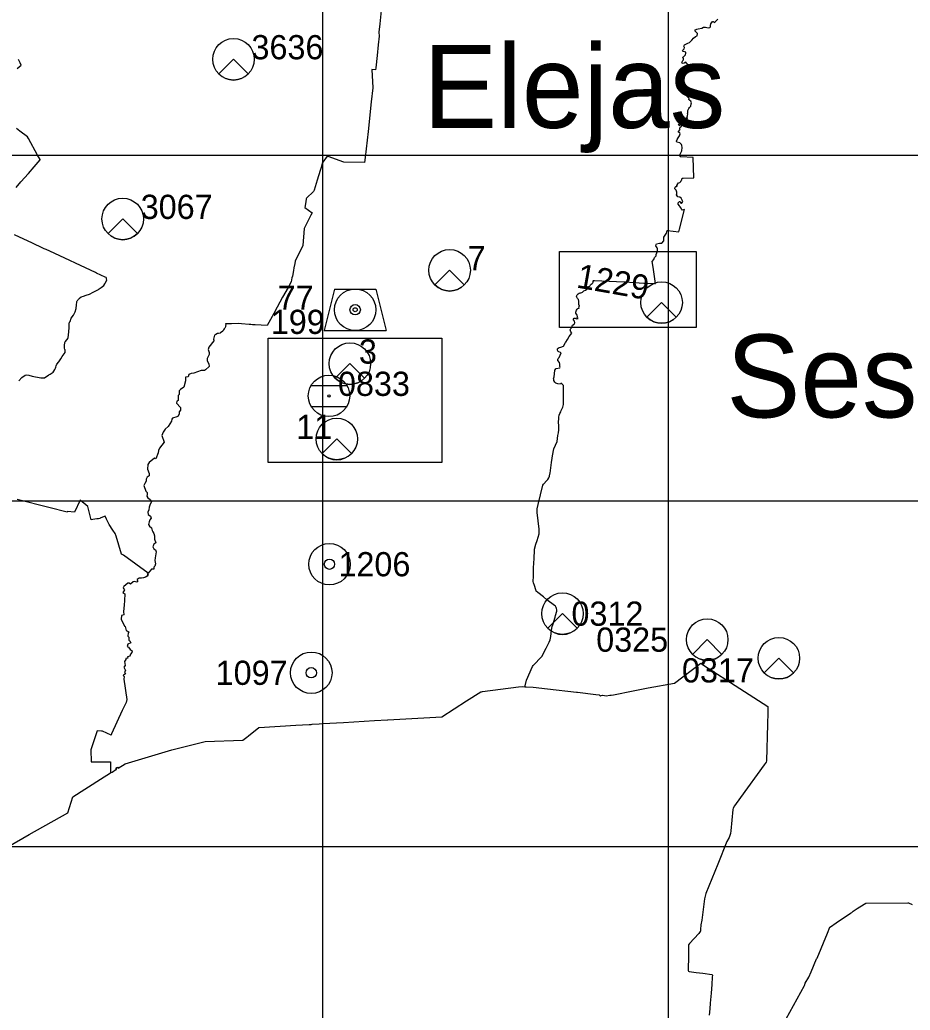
# Model space of a CAD drawing. Extents: x 459000 to 506121, y 222400 to 317452.
# Drawn here: x 475618 to 488504, y 242637 to 256960 of the extents above; entities that cross this region are included whole.
import ezdxf

# ---------------------------------------------------------------- set-up
doc = ezdxf.new("R2010")
doc.units = 0
for name, color, linetype in [('Default', 7, 'Continuous'), ('fundamentalie_reperi', 7, 'Continuous'), ('grunts_reperi', 7, 'Continuous'), ('pagastu_nosaukumi', 7, 'Continuous'), ('pagastu_robezas', 7, 'Continuous'), ('Ramis', 7, 'Continuous'), ('savietotie_ar_gp_punktiem', 7, 'Continuous'), ('sienas_reperi', 7, 'Continuous'), ('valsts_robeza', 7, 'Continuous')]:
    doc.layers.add(name, color=color, linetype=linetype)

msp = doc.modelspace()

# ---------------------------------------------------------------- linework, layer by layer
at = {"layer": 'Default'}
for points in [[(483429, 253611), (485407, 253611), (485407, 252512), (483429, 252512)], [(479212, 252355), (481727, 252355), (481727, 250558), (479212, 250558)]]:
    msp.add_lwpolyline(points, close=True, dxfattribs=at)
at = {"layer": 'fundamentalie_reperi'}
for p, q in [((480172, 253067), (480022, 252467)), ((480172, 253067), (480772, 253067)), ((480772, 253067), (480922, 252467)), ((480022, 252467), (480922, 252467))]:
    msp.add_line(p, q, dxfattribs=at)
msp.add_circle((480472, 252767), 30, dxfattribs=at)
at = {"layer": 'grunts_reperi'}
for centre, radius in [((480472, 252767), 300), ((480472, 252767), 75), ((480100, 249087), 300), ((480100, 249087), 75), ((479837, 247517), 300), ((479837, 247517), 75)]:
    msp.add_circle(centre, radius, dxfattribs=at)
at = {"layer": 'pagastu_robezas'}
for points in [[(480850, 257097), (480828, 256904), (480813, 256782), (480820, 256722), (480806, 256597), (480789, 256442), (480770, 256265), (480767, 256237), (480713, 256241), (480727, 255975), (480704, 255773), (480658, 255345), (480618, 254971), (480608, 254898), (480310, 254903), (480080, 254983), (480067, 254989), (480002, 254899), (480001, 254895), (479979, 254823), (479966, 254779), (479924, 254642), (479879, 254494), (479871, 254476), (479766, 254382), (479762, 254372), (479756, 254329), (479745, 254245), (479849, 254169), (479832, 254137), (479832, 254135), (479733, 253942), (479716, 253696), (479605, 253469), (479598, 253435), (479585, 253374), (479577, 253334), (479563, 253253), (479557, 253227), (479545, 253172), (479500, 253090), (479421, 252948), (479342, 252806), (479294, 252715), (479200, 252538), (479024, 252549), (478987, 252551), (478963, 252553), (478939, 252554), (478828, 252562), (478781, 252566), (478683, 252564), (478594, 252564), (478599, 252542), (478597, 252536), (478594, 252519), (478588, 252502), (478576, 252490), (478565, 252476), (478556, 252459), (478524, 252433), (478524, 252433), (478520, 252430), (478494, 252425), (478481, 252422), (478454, 252410), (478437, 252397), (478430, 252380), (478424, 252343), (478428, 252327), (478426, 252317), (478354, 252224), (478346, 252190), (478359, 252149), (478361, 252120), (478328, 252064), (478328, 252027), (478354, 251984), (478359, 251947), (478307, 251899), (478289, 251887), (478242, 251887), (478136, 251848), (478098, 251846), (478064, 251831), (478056, 251799), (478017, 251790), (478015, 251738), (477992, 251645), (477942, 251614), (477924, 251592), (477924, 251541), (477911, 251529), (477909, 251456), (477891, 251446), (477885, 251417), (477945, 251352), (477942, 251313), (477924, 251289), (477927, 251260), (477909, 251228), (477893, 251218), (477829, 251201), (477818, 251184), (477816, 251158), (477764, 251078), (477722, 251039), (477694, 250995), (477673, 250949), (477710, 250852), (477642, 250765), (477624, 250733), (477622, 250699), (477585, 250612), (477567, 250619), (477490, 250556), (477469, 250529), (477466, 250461), (477492, 250398), (477490, 250367), (477461, 250345), (477448, 250315), (477448, 250286), (477430, 250252), (477415, 250227), (477443, 250142), (477464, 250123), (477464, 250096), (477456, 250072), (477472, 250048), (477505, 250021), (477526, 249990), (477503, 249956), (477490, 249912), (477487, 249873), (477472, 249842), (477477, 249808), (477508, 249781), (477521, 249754), (477500, 249730), (477490, 249698), (477482, 249662), (477497, 249635), (477523, 249614), (477536, 249575), (477544, 249553), (477560, 249529), (477570, 249497), (477570, 249451), (477585, 249398), (477560, 249378), (477544, 249339), (477560, 249310), (477583, 249296), (477593, 249267), (477578, 249177), (477575, 249140), (477583, 249092), (477572, 249058), (477557, 249043), (477557, 249017), (477523, 249017), (477474, 248958)], [(482928, 247316), (482930, 247327), (482949, 247408), (483040, 247609), (483049, 247620), (483063, 247636), (483161, 247738), (483171, 247752), (483235, 247872), (483260, 247923), (483281, 247960), (483292, 247992), (483302, 248040), (483312, 248135), (483324, 248186), (483332, 248211), (483366, 248322), (483370, 248343), (483390, 248408), (483391, 248426), (483387, 248446), (483382, 248462), (483370, 248478), (483358, 248489), (483247, 248573), (483197, 248613), (483113, 248680), (483093, 248699), (483084, 248717), (483065, 248779), (483053, 248816), (483050, 248838), (483052, 248913), (483054, 248988), (483055, 249035), (483061, 249171), (483065, 249289), (483067, 249303), (483086, 249375), (483105, 249431), (483133, 249525), (483134, 249543), (483137, 249593), (483107, 249836), (483104, 249887), (483119, 249950), (483187, 250230), (483197, 250247), (483246, 250297), (483260, 250314), (483273, 250335), (483284, 250361), (483291, 250396), (483292, 250404), (483312, 250556), (483322, 250620), (483328, 250652), (483348, 250757), (483395, 250860), (483400, 250904), (483406, 250946), (483412, 250985), (483419, 251030), (483420, 251086), (483416, 251141), (483418, 251195), (483419, 251215), (483424, 251241), (483434, 251265), (483446, 251290), (483455, 251309), (483465, 251327), (483478, 251359), (483486, 251395), (483485, 251398), (483487, 251468), (483485, 251582), (483485, 251644), (483489, 251651), (483485, 251670), (483475, 251680), (483469, 251690), (483466, 251692), (483461, 251699), (483459, 251702), (483447, 251701), (483442, 251693), (483406, 251694), (483377, 251704), (483362, 251720), (483347, 251746), (483346, 251758), (483344, 251774), (483346, 251781), (483351, 251799), (483357, 251842), (483361, 251895), (483381, 251915), (483432, 251925), (483440, 251937), (483434, 251945), (483436, 251967), (483436, 251979), (483427, 252003), (483407, 252032), (483405, 252046), (483408, 252061), (483422, 252076), (483452, 252143), (483409, 252164), (483401, 252183), (483401, 252203), (483411, 252210), (483426, 252220), (483446, 252228), (483489, 252241), (483518, 252294), (483520, 252298), (483543, 252335), (483570, 252380), (483588, 252406), (483606, 252428), (483593, 252449), (483582, 252477), (483592, 252494), (483605, 252512), (483616, 252543), (483642, 252560), (483650, 252576), (483644, 252600), (483629, 252619), (483643, 252644), (483658, 252644), (483675, 252634), (483697, 252639), (483685, 252651), (483690, 252670), (483683, 252689), (483673, 252703), (483667, 252719), (483663, 252731), (483669, 252748), (483675, 252762), (483685, 252776), (483695, 252787), (483712, 252790), (483708, 252808), (483718, 252818), (483711, 252845), (483710, 252869), (483710, 252891), (483705, 252915), (483689, 252932), (483679, 252949), (483677, 252962), (483686, 252981), (483701, 252996), (483715, 253006), (483726, 253010), (483740, 253014), (483751, 253015), (483754, 253016), (483760, 253019), (483770, 253029), (483779, 253040), (483807, 253051), (483823, 253063), (483824, 253071), (483815, 253080), (483814, 253084), (483825, 253094), (483837, 253102), (483846, 253098), (483866, 253110), (483877, 253125), (483888, 253135), (483902, 253146), (483915, 253159), (483913, 253169), (483920, 253177), (483922, 253182), (483916, 253188), (483936, 253188), (484362, 253172), (484368, 253172), (484369, 253172), (484375, 253171), (484650, 253151), (484662, 253150), (484806, 253148), (484816, 253148), (484784, 253382), (484772, 253466), (484792, 253492), (484802, 253521), (484827, 253548), (484829, 253554), (484830, 253564), (484845, 253612), (484847, 253654), (484843, 253662), (484821, 253691), (484826, 253710), (484833, 253722), (484875, 253731), (484910, 253732), (484940, 253764), (484938, 253815), (484979, 253876), (484986, 253912), (484992, 253911), (485156, 253896), (485166, 253933), (485238, 254216), (485224, 254214), (485202, 254205), (485201, 254213), (485190, 254235), (485170, 254260), (485164, 254268), (485145, 254293), (485147, 254312), (485158, 254323), (485166, 254334), (485177, 254331), (485181, 254320), (485187, 254310), (485192, 254306), (485203, 254316), (485213, 254332), (485200, 254361), (485190, 254382), (485171, 254396), (485140, 254402), (485121, 254430), (485125, 254445), (485128, 254455), (485125, 254467), (485115, 254495), (485107, 254504), (485099, 254514), (485096, 254527), (485105, 254538), (485110, 254546), (485112, 254553), (485122, 254543), (485132, 254552), (485128, 254568), (485131, 254574), (485141, 254589), (485151, 254602), (485169, 254607), (485183, 254623), (485192, 254636), (485198, 254646), (485205, 254671), (485217, 254670), (485374, 254677), (485364, 254967), (485185, 254977), (485181, 254977), (485177, 254984), (485176, 254986), (485176, 255017), (485199, 255063), (485202, 255114), (485198, 255141), (485195, 255157), (485170, 255183), (485126, 255192), (485121, 255206), (485131, 255228), (485145, 255254), (485165, 255284), (485177, 255312), (485171, 255325), (485150, 255335), (485149, 255344), (485173, 255375), (485169, 255383), (485170, 255391), (485172, 255400), (485183, 255413), (485196, 255419), (485193, 255427), (485203, 255435), (485204, 255442), (485203, 255446), (485194, 255453), (485181, 255448), (485176, 255434), (485165, 255428), (485157, 255434), (485149, 255447), (485156, 255453), (485166, 255454), (485177, 255466), (485176, 255478), (485182, 255494), (485188, 255492), (485195, 255493), (485202, 255521), (485211, 255533), (485226, 255531), (485236, 255533), (485254, 255535), (485268, 255542), (485270, 255534), (485279, 255534), (485280, 255542), (485274, 255548), (485275, 255558), (485280, 255573), (485284, 255598), (485280, 255604), (485281, 255611), (485287, 255619), (485287, 255636), (485286, 255650), (485302, 255678), (485312, 255692), (485329, 255710), (485334, 255745), (485339, 255760), (485328, 255783), (485317, 255794), (485301, 255807), (485304, 255823), (485265, 255862), (485228, 255894), (485222, 255910), (485215, 255930), (485206, 255940), (485180, 255947), (485170, 255951), (485153, 255979), (485149, 256005), (485155, 256031), (485155, 256045), (485142, 256062), (485155, 256095), (485167, 256104), (485201, 256130), (485208, 256135), (485232, 256170), (485234, 256178), (485239, 256202), (485243, 256222), (485250, 256233), (485263, 256244), (485280, 256246), (485291, 256244), (485306, 256230), (485328, 256223), (485340, 256217), (485360, 256220), (485364, 256229), (485370, 256246), (485371, 256265), (485367, 256271), (485361, 256282), (485326, 256289), (485295, 256304), (485273, 256321), (485267, 256334), (485255, 256346), (485244, 256342), (485232, 256331), (485217, 256326), (485206, 256331), (485197, 256342), (485204, 256352), (485212, 256370), (485223, 256382), (485221, 256395), (485216, 256418), (485223, 256426), (485251, 256455), (485259, 256477), (485256, 256492), (485237, 256497), (485217, 256502), (485208, 256510), (485216, 256522), (485231, 256538), (485237, 256560), (485228, 256579), (485234, 256588), (485240, 256596), (485288, 256624), (485312, 256631), (485342, 256667), (485368, 256693), (485398, 256719), (485423, 256729), (485427, 256761), (485407, 256779), (485389, 256800), (485398, 256815), (485416, 256824), (485438, 256829), (485488, 256840), (485514, 256852), (485541, 256856), (485562, 256847), (485584, 256844), (485605, 256849), (485615, 256860), (485614, 256878), (485617, 256901), (485641, 256934), (485654, 256938), (485662, 256931), (485675, 256922), (485684, 256930), (485697, 256945), (485720, 256971)], [(475580, 256254), (475637, 256304), (475624, 256336), (475599, 256384)], [(475564, 254534), (475633, 254616), (475742, 254736), (475826, 254835), (475853, 254866), (475914, 254937), (475911, 254942), (475873, 255003), (475744, 255242), (475728, 255270), (475620, 255351), (475573, 255388)], [(475604, 251740), (475650, 251788), (475698, 251820), (475715, 251825), (475748, 251821), (475799, 251806), (475922, 251781), (475978, 251783), (476024, 251816), (476039, 251820), (476041, 251824), (476056, 251833), (476085, 251854), (476101, 251864), (476113, 251880), (476127, 251903), (476135, 251921), (476139, 251938), (476144, 251958), (476155, 251981), (476181, 252014), (476212, 252057), (476233, 252092), (476233, 252093), (476259, 252128), (476276, 252151), (476277, 252166), (476274, 252187), (476268, 252194), (476267, 252209), (476264, 252249), (476272, 252294), (476274, 252303), (476306, 252337), (476312, 252349), (476317, 252362), (476326, 252448), (476329, 252466), (476335, 252491), (476333, 252539), (476331, 252564), (476337, 252585), (476345, 252597), (476363, 252647), (476395, 252690), (476422, 252738), (476433, 252785), (476439, 252836), (476443, 252876), (476446, 252888), (476451, 252898), (476457, 252907), (476464, 252916), (476472, 252924), (476480, 252931), (476487, 252939), (476508, 252952), (476538, 252963), (476577, 252976), (476627, 252994), (476682, 253021), (476747, 253056), (476756, 253061), (476766, 253068), (476798, 253088), (476833, 253117), (476847, 253143), (476852, 253152), (476876, 253194), (476873, 253212), (476871, 253224), (476867, 253232), (476854, 253238), (476728, 253298), (476714, 253304), (476051, 253612), (476002, 253636), (475973, 253650), (475954, 253659), (475800, 253731), (475541, 253851)], [(477474, 248958), (477118, 249216), (477092, 249234), (477014, 249492), (476997, 249529), (476964, 249579), (476911, 249662), (476871, 249738), (476853, 249782), (476790, 249758), (476783, 249752), (476779, 249749), (476759, 249744), (476734, 249743), (476705, 249739), (476675, 249732), (476653, 249728), (476605, 249922), (476494, 250014), (476408, 249842), (476308, 249847), (476305, 249842), (476040, 249908), (475582, 250022)], [(477474, 248958), (477464, 248945), (477475, 248936), (477460, 248914), (477439, 248900), (477408, 248890), (477381, 248884), (477348, 248883), (477318, 248867), (477317, 248861), (477324, 248846), (477324, 248833), (477308, 248827), (477284, 248839), (477257, 248831), (477219, 248799), (477200, 248811), (477180, 248813), (477126, 248767), (477117, 248756), (477114, 248750), (477118, 248735), (477133, 248717), (477118, 248693), (477118, 248693), (477109, 248679), (477139, 248660), (477133, 248564), (477128, 248494), (477118, 248403), (477122, 248353), (477089, 248344), (477083, 248292), (477132, 248190), (477144, 248185), (477157, 248126), (477197, 248110), (477185, 248096), (477184, 248047), (477197, 248030), (477195, 247987), (477213, 247981), (477225, 247948), (477183, 247930), (477174, 247897), (477192, 247887), (477216, 247854), (477243, 247832), (477239, 247809), (477220, 247784), (477213, 247759), (477179, 247748), (477181, 247729), (477155, 247724), (477151, 247707), (477133, 247682), (477142, 247624), (477124, 247596), (477147, 247550), (477132, 247532), (477148, 247503), (477125, 247489), (477112, 247477), (477128, 247461), (477122, 247424), (477166, 247130), (477157, 247089), (477102, 246969), (476946, 246632), (476940, 246613), (476814, 246674), (476802, 246672), (476737, 246675), (476646, 246403), (476650, 246230), (476792, 246231), (476799, 246231), (476828, 246231), (476930, 246227), (476930, 246077), (476931, 246071)]]:
    msp.add_lwpolyline(points, dxfattribs=at)
at = {"layer": 'Ramis'}
for p, q in [((480000, 310000), (480000, 240000)), ((485000, 310000), (485000, 240000)), ((505000, 255000), (460000, 255000)), ((505000, 250000), (460000, 250000)), ((505000, 245000), (460000, 245000))]:
    msp.add_line(p, q, dxfattribs=at)
at = {"layer": 'savietotie_ar_gp_punktiem'}
for p, q in [((479834, 251672), (480352, 251672)), ((479836, 251366), (480350, 251366))]:
    msp.add_line(p, q, dxfattribs=at)
for radius in [300, 16]:
    msp.add_circle((480093, 251521), radius, dxfattribs=at)
at = {"layer": 'sienas_reperi'}
for p, q in [((478711, 256389), (478499, 256177)), ((478923, 256177), (478711, 256389)), ((477108, 254080), (476896, 253868)), ((477320, 253868), (477108, 254080)), ((481839, 253338), (481627, 253126)), ((482051, 253126), (481839, 253338)), ((484907, 252871), (484695, 252659)), ((485119, 252659), (484907, 252871)), ((480396, 251988), (480184, 251776)), ((480608, 251776), (480396, 251988)), ((480206, 250898), (479994, 250686)), ((480419, 250686), (480206, 250898)), ((483472, 248372), (483260, 248160)), ((483684, 248160), (483472, 248372)), ((485567, 247996), (485355, 247783)), ((485780, 247783), (485567, 247996)), ((486604, 247727), (486392, 247515)), ((486816, 247515), (486604, 247727))]:
    msp.add_line(p, q, dxfattribs=at)
for centre in [(478711, 256389), (477108, 254080), (481839, 253338), (484907, 252871), (480396, 251988), (480206, 250898), (483472, 248372), (485567, 247996), (486604, 247727)]:
    msp.add_circle(centre, 300, dxfattribs=at)
for centre in [(478711, 256389), (477108, 254080), (481839, 253338), (484907, 252871), (480396, 251988), (480206, 250898), (483472, 248372), (485567, 247996), (486604, 247727)]:
    msp.add_arc(centre, 300, 225, 315, dxfattribs=at)
at = {"layer": 'valsts_robeza'}
for points in [[(482928, 247316), (482932, 247316), (482945, 247316), (483048, 247307), (483254, 247286), (483674, 247236), (483688, 247235), (483691, 247235), (483957, 247205), (484005, 247197), (484021, 247177), (484034, 247186), (484052, 247191), (484058, 247191), (484106, 247185), (484158, 247192), (484177, 247195), (484208, 247200), (484257, 247210), (484445, 247248), (484711, 247298), (485095, 247366), (485473, 247656), (485514, 247628), (486038, 247290), (486442, 247027), (486442, 246936), (486438, 246772), (486423, 246243), (486419, 246226), (486407, 246205), (486390, 246184), (486049, 245715), (485962, 245594), (485942, 245559), (485936, 245540), (485907, 245232), (485904, 245195), (485894, 245164), (485883, 245137), (485852, 245076), (485720, 244750), (485720, 244750), (485547, 244325), (485525, 244246), (485487, 243941), (485476, 243870), (485471, 243803), (485467, 243779), (485465, 243773), (485444, 243748), (485310, 243600), (485298, 243584), (485294, 243569), (485294, 243427), (485293, 243212), (485295, 243200), (485305, 243195), (485409, 243183), (485505, 243171), (485634, 243155), (485640, 243150), (485642, 243144), (485640, 243114), (485632, 243011), (485622, 242882), (485611, 242741), (485604, 242655), (485597, 242567)], [(476931, 246071), (476941, 246073), (476954, 246081), (477007, 246117), (477020, 246120), (477018, 246123), (477007, 246138), (477032, 246152), (477041, 246138), (477144, 246202), (477819, 246402), (478301, 246521), (478848, 246542), (478904, 246587), (478928, 246606), (479079, 246727), (479084, 246727), (479611, 246758), (479806, 246770), (479837, 246771), (479850, 246772), (479950, 246778), (480004, 246781), (480004, 246781), (480303, 246798), (480753, 246826), (480939, 246835), (480945, 246835), (481726, 246882), (482082, 247109), (482290, 247241), (482299, 247241), (482313, 247246), (482837, 247314), (482887, 247317), (482928, 247316)], [(475444, 245002), (475756, 245177), (476315, 245491), (476387, 245723), (476388, 245724), (476785, 245979), (476931, 246071), (476931, 246071)], [(486711, 242514), (486973, 242994), (486979, 243005), (486986, 243027), (487035, 243114), (487070, 243190), (487150, 243380), (487158, 243392), (487309, 243750), (487343, 243838), (487349, 243844), (487433, 243902), (487641, 244039), (487660, 244052), (487677, 244068), (487736, 244106), (487836, 244173), (487861, 244185), (488471, 244191), (488479, 244190), (488532, 244165)]]:
    msp.add_lwpolyline(points, dxfattribs=at)

# ---------------------------------------------------------------- texts
at = {"layer": 'fundamentalie_reperi'}
msp.add_text('77  ', height=350, dxfattribs=at).set_placement((479350, 252767))
at = {"layer": 'grunts_reperi'}
for s, p in [('199  ', (479251, 252417)), (' 1206', (480100, 248912)), ('1097 ', (478453, 247342))]:
    msp.add_text(s, height=350, dxfattribs=at).set_placement(p)
at = {"layer": 'pagastu_nosaukumi'}
for s, p in [('Elejas', (481457, 255397)), ('Sesavas', (485844, 251210))]:
    msp.add_text(s, height=1200, dxfattribs=at).set_placement(p)
at = {"layer": 'savietotie_ar_gp_punktiem'}
msp.add_text(' 0833', height=350, dxfattribs=at).set_placement((480093, 251521))
at = {"layer": 'sienas_reperi'}
for s, p in [('  3636', (478711, 256389)), ('  3067', (477108, 254080)), ('  7', (481839, 253338)), (' 3', (480396, 251988)), ('11  ', (479620, 250898)), (' 0312', (483472, 248197)), ('0325 ', (483960, 247821)), ('0317 ', (485201, 247377))]:
    msp.add_text(s, height=350, dxfattribs=at).set_placement(p)
msp.add_text('1229 ', height=350, rotation=350, dxfattribs=at).set_placement((483662, 253090))

doc.saveas('drawing.dxf')
